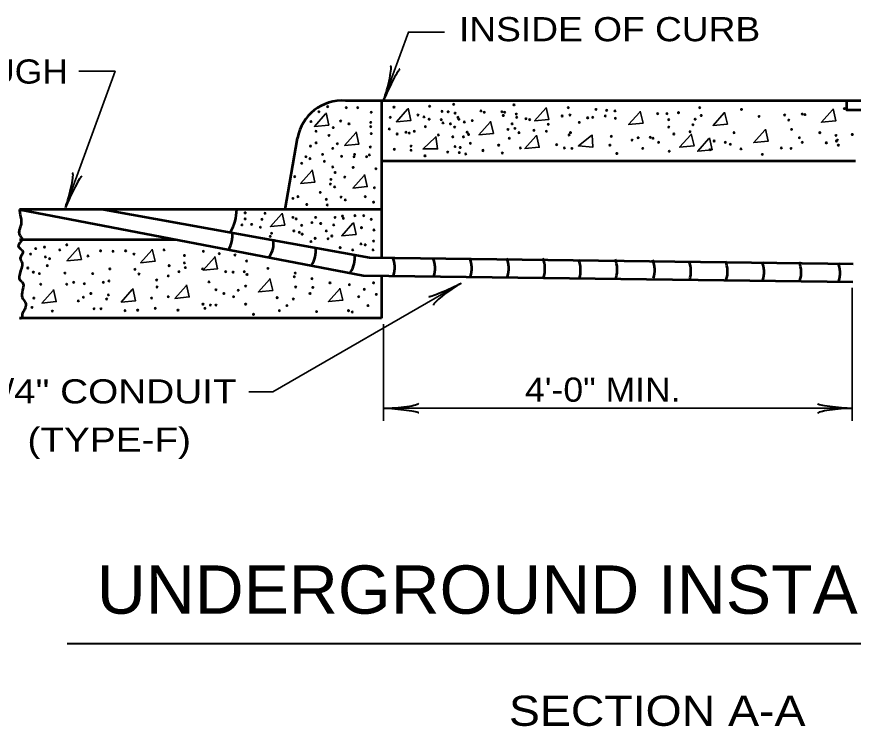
# Model space of a CAD drawing. Extents: x -58 to 622, y -372 to 68.
# Drawn here: x 3.2 to 72.5, y -96.1 to -37.4 of the extents above; entities that cross this region are included whole.
import ezdxf
from ezdxf.enums import TextEntityAlignment as Align

# ---------------------------------------------------------------- set-up
doc = ezdxf.new("R2010")
doc.units = 0
doc.header["$LTSCALE"] = 0.8
doc.layers.add('1', color=7, linetype='Continuous', lineweight=35)

msp = doc.modelspace()

# ---------------------------------------------------------------- linework, layer by layer
at = {"layer": '1', "lineweight": 53}
for p, q in [((95.4567, -44.3181), (30.4567, -44.3181)), ((33.4567, -44.3181), (33.4567, -57.3237)), ((25.4567, -53.3181), (26.4986, -47.4093)), ((72.7067, -49.3181), (33.4567, -49.3181)), ((33.4567, -53.3181), (3.4567, -53.3181)), ((3.4567, -53.3181), (31.9376, -58.7988)), ((10.4567, -53.3181), (32.4567, -57.3053)), ((3.4567, -55.8181), (16.448, -55.8181)), ((32.4567, -57.3053), (72.5202, -57.8181)), ((31.9376, -58.7988), (72.501, -59.318)), ((33.4567, -58.7824), (33.4567, -62.3181)), ((33.4567, -62.3181), (3.4567, -62.3181))]:
    msp.add_line(p, q, dxfattribs=at)
at = {"layer": '1'}
for p, q in [((72.4397, -59.8188), (72.4397, -70.8188)), ((33.6269, -62.8061), (33.6269, -70.8188)), ((33.6609, -69.7865), (72.4412, -69.7865))]:
    msp.add_line(p, q, dxfattribs=at)
at = {"layer": '1', "lineweight": 40}
msp.add_line((7.4085, -89.2559), (100.8059, -89.2559), dxfattribs=at)
at = {"layer": '1'}
for points in [[(33.6255, -44.2669), (35.6776, -38.6287), (38.6776, -38.6287)], [(7.2722, -53.1423), (11.3764, -41.866), (8.3764, -41.866)], [(35.6102, -45.0193), (34.6888, -46.0558), (35.8788, -45.9407), (35.6485, -44.9426)], [(47.0498, -44.9426), (46.1285, -45.9791), (47.3185, -45.8639), (47.0882, -44.8658)], [(70.812, -45.0577), (69.8907, -46.0942), (71.0807, -45.9791), (70.8503, -44.981)], [(28.8155, -45.4032), (27.8942, -46.4397), (29.0842, -46.3246), (28.8538, -45.3265)], [(54.8426, -45.2497), (53.9213, -46.2862), (55.1112, -46.171), (54.8809, -45.1729)], [(61.8292, -45.3264), (60.9079, -46.3629), (62.0979, -46.2477), (61.8676, -45.2497)], [(42.4432, -46.0942), (41.5219, -47.1307), (42.7119, -47.0156), (42.4816, -46.0175)], [(31.3107, -46.9771), (30.3893, -48.0136), (31.5793, -47.8984), (31.349, -46.9003)], [(59.0652, -47.1307), (58.1439, -48.1672), (59.3339, -48.052), (59.1036, -47.0539)], [(65.2073, -46.7468), (64.286, -47.7833), (65.476, -47.6682), (65.2457, -46.6701)], [(37.9037, -47.3589), (36.8955, -48.3112), (38.091, -48.3002), (37.9485, -47.2858)], [(46.2437, -47.2458), (45.3223, -48.2823), (46.5123, -48.1672), (46.282, -47.1691)], [(50.8516, -47.1979), (49.7642, -48.0587), (50.9562, -48.1519), (50.9026, -47.129)], [(60.5674, -47.4546), (59.6461, -48.4911), (60.8361, -48.3759), (60.6058, -47.3778)], [(27.6638, -50.1249), (26.7425, -51.1614), (27.9325, -51.0463), (27.7022, -50.0482)], [(32.0017, -50.5088), (31.0803, -51.5453), (32.2703, -51.4302), (32.04, -50.4321)], [(25.1686, -53.695), (24.2472, -54.7315), (25.4372, -54.6163), (25.2069, -53.6182)], [(31.0803, -54.4628), (30.159, -55.4993), (31.349, -55.3842), (31.1187, -54.3861)], [(8.3163, -56.5358), (7.3949, -57.5722), (8.5849, -57.4571), (8.3546, -56.459)], [(14.4199, -56.6893), (13.4986, -57.7258), (14.6886, -57.6107), (14.4582, -56.6126)], [(19.6023, -57.3035), (18.681, -58.34), (19.871, -58.2248), (19.6407, -57.2267)], [(17.2607, -59.6452), (16.3393, -60.6817), (17.5293, -60.5665), (17.299, -59.5684)], [(40.0432, -59.4234), (24.4548, -68.4234), (22.4548, -68.4234)], [(24.1705, -59.1077), (23.2492, -60.1442), (24.4392, -60.0291), (24.2088, -59.031)], [(6.2432, -60.0291), (5.3219, -61.0656), (6.5119, -60.9504), (6.2816, -59.9523)], [(12.8077, -59.9523), (11.8863, -60.9888), (13.0763, -60.8737), (12.846, -59.8756)], [(29.9671, -59.9139), (29.0457, -60.9504), (30.2357, -60.8352), (30.0054, -59.8372)]]:
    msp.add_lwpolyline(points, dxfattribs=at)
at = {"layer": '1', "lineweight": 53}
msp.add_lwpolyline([(71.9567, -44.3181), (71.9567, -45.0681), (86.4567, -45.0681), (86.4567, -44.3181)], dxfattribs=at)
at = {"layer": '1'}
for centre in [(28.9883, -44.8078), (30.5238, -44.8846), (31.4836, -44.8846), (34.4778, -44.8462), (37.4337, -44.7694), (39.4299, -44.6158), (44.4204, -44.6542), (48.9118, -44.8846), (51.2151, -45.0382), (59.814, -44.8846), (63.2689, -45.0382), (71.7911, -44.9613), (28.2589, -45.2301), (32.5968, -45.2685), (34.1707, -45.6908), (36.474, -45.4988), (36.9731, -45.6523), (38.4703, -45.1917), (38.9692, -45.2301), (39.5451, -45.3453), (39.7754, -45.6908), (41.6948, -45.1533), (41.9636, -45.2685), (43.4223, -45.2301), (43.5375, -45.5372), (43.6527, -45.2685), (44.6123, -45.422), (44.6507, -45.6908), (48.4127, -45.5756), (49.0653, -45.4988), (50.5241, -45.7291), (50.9463, -45.6908), (51.9828, -45.5756), (52.098, -45.1149), (52.789, -45.1533), (52.8274, -45.7675), (56.3207, -45.3837), (57.0885, -45.3837), (58.0482, -45.3068), (59.9292, -45.5372), (64.7277, -45.614), (66.839, -45.4988), (68.2977, -45.422), (68.5281, -45.4604), (27.6063, -46.0362), (30.0632, -45.9978), (30.7542, -46.2282), (32.5584, -46.113), (32.5584, -46.4585), (37.0883, -46.4585), (37.3954, -45.8442), (38.3935, -45.8827), (38.547, -46.1514), (39.1612, -46.2282), (39.8522, -45.8442), (40.3128, -46.0746), (40.9655, -45.9594), (44.2668, -46.2282), (45.4185, -45.8059), (45.7256, -45.8827), (47.2611, -46.2666), (49.8331, -46.113), (57.242, -45.8827), (59.2382, -46.3049), (59.4302, -45.8442), (67.1845, -45.9211), (28.0287, -46.8424), (29.449, -46.5353), (32.5968, -47.0343), (34.0939, -46.6505), (34.7465, -47.0727), (35.4759, -46.9192), (35.7447, -46.9959), (36.1669, -46.8424), (38.1632, -47.1495), (39.5067, -46.4969), (40.5432, -46.9192), (40.6583, -47.1111), (43.9213, -46.6888), (44.4972, -46.6121), (44.8427, -46.9576), (46.0711, -46.7656), (47.1076, -46.8424), (48.9886, -47.1495), (49.1037, -46.9576), (57.242, -46.4969), (57.6642, -47.0727), (59.0078, -46.8807), (62.6547, -46.9576), (67.4148, -46.6888), (69.7565, -46.9576), (72.4437, -47.1111), (28.0287, -47.8021), (29.1035, -47.1879), (39.3532, -47.303), (40.2361, -47.303), (40.8119, -47.8405), (44.0365, -47.4182), (52.4819, -47.2647), (54.2093, -47.5718), (54.7084, -47.3798), (55.7065, -47.3414), (55.9368, -47.4182), (56.3975, -47.7637), (61.0041, -47.6485), (61.9253, -47.7637), (68.0675, -47.3798), (68.2977, -47.7637), (70.294, -47.8021), (71.1001, -47.1878), (71.1385, -47.6485), (71.2152, -47.5718), (27.568, -48.0708), (29.4106, -48.2627), (29.7945, -47.8789), (32.52, -48.1476), (34.5162, -48.3395), (35.8982, -48.0708), (35.8982, -48.4163), (39.5451, -48.1092), (39.9674, -48.186), (41.8484, -48.4162), (41.8484, -48.4547), (43.1536, -47.994), (44.9578, -48.2243), (47.9521, -47.9557), (48.6047, -48.2243), (49.2189, -48.2627), (52.3667, -47.994), (55.0922, -48.2627), (57.2804, -48.4931), (60.6586, -48.3779), (62.3477, -47.9172), (63.2306, -48.3011), (66.5703, -48.2243), (67.3765, -48.2627), (71.2921, -47.994), (27.1841, -48.9537), (27.5296, -49.1073), (28.5661, -48.7618), (30.14, -48.9153), (31.1764, -48.9537), (31.2148, -48.7618), (32.2129, -48.9537), (32.4432, -48.8002), (37.0498, -48.877), (38.9309, -48.5698), (39.8906, -48.6082), (40.428, -48.7234), (43.4607, -48.6466), (52.9426, -48.685), (64.9964, -48.7617), (26.8386, -49.4912), (28.7196, -49.3377), (29.4106, -49.7982), (31.0997, -49.8367), (32.9807, -49.9518), (26.2628, -50.6044), (29.6025, -50.2589), (30.4087, -50.6428), (29.2187, -51.2187), (29.2571, -50.8347), (28.3741, -51.9097), (29.5642, -51.449), (32.8655, -51.5257), (26.1092, -52.4087), (26.5315, -52.2551), (28.8732, -52.4854), (30.1016, -52.2935), (30.4471, -52.5238), (32.0977, -52.2551), (32.7888, -52.7157), (27.2608, -52.9078), (28.9499, -52.9461), (22.1552, -53.5987), (22.1552, -54.0977), (23.8059, -53.6371), (26.1092, -53.9826), (26.3779, -54.0977), (27.9902, -53.9826), (29.6025, -53.9826), (30.2167, -53.8674), (30.2935, -54.0593), (31.2532, -53.829), (31.9826, -53.829), (21.8865, -54.5968), (22.6927, -54.5584), (23.4221, -54.7888), (23.5373, -54.1362), (26.8386, -54.6352), (27.6832, -54.4048), (28.4125, -54.4817), (29.4873, -54.5968), (32.5968, -54.1362), (24.3433, -55.2877), (26.186, -55.0958), (26.6467, -55.211), (26.877, -55.3646), (28.8732, -55.0958), (31.7907, -54.8272), (32.8272, -55.0191), (24.2282, -55.5565), (27.6063, -55.9787), (27.9518, -55.7101), (29.0267, -55.7484), (29.3338, -55.5181), (31.7523, -56.1707), (32.7888, -55.9404), (4.8038, -56.5547), (5.5332, -56.4395), (6.8, -56.6698), (7.3758, -56.2475), (10.1782, -56.7466), (11.2147, -56.785), (12.2512, -56.7466), (15.4373, -56.6698), (18.7003, -56.785), (30.0248, -56.4778), (31.0612, -56.6698), (32.0977, -56.2475), (32.7503, -56.6698), (4.3816, -57.0153), (5.61, -57.2457), (5.9555, -57.3992), (9.1417, -57.1688), (12.9422, -57.0153), (17.1264, -57.1305), (20.0055, -56.9769), (21.3107, -57.0921), (4.1513, -58.1669), (5.7636, -57.975), (10.9459, -58.2437), (15.8596, -57.975), (17.1264, -57.7447), (17.2032, -58.1286), (18.6236, -58.2437), (22.2704, -57.5911), (24.0362, -58.2053), (4.6119, -58.5124), (5.1109, -58.6276), (7.2223, -58.5892), (9.5256, -58.6276), (13.0189, -58.2821), (13.3644, -58.666), (15.7828, -58.8196), (16.6657, -58.4741), (20.543, -58.4741), (21.1572, -58.5124), (22.0785, -58.4741), (22.3088, -58.7044), (26.2244, -58.8963), (26.3012, -58.5892), (5.2261, -59.5105), (7.3758, -59.5105), (7.9517, -59.357), (8.8346, -59.4722), (10.4085, -59.357), (10.8692, -59.2418), (14.8232, -59.165), (19.161, -59.3186), (27.6832, -59.0498), (29.1802, -59.3953), (30.7926, -59.5489), (32.7888, -59.3953), (9.372, -60.2782), (14.8615, -59.7408), (19.7368, -59.9712), (20.3894, -60.2782), (21.5794, -60.0096), (22.1937, -59.6641), (26.3396, -59.7408), (27.5296, -60.2782), (27.7599, -59.7792), (32.021, -59.9328), (4.6503, -60.6622), (8.3356, -60.8925), (8.7578, -60.5854), (10.6772, -60.7389), (10.8308, -60.3934), (14.4008, -60.6622), (15.7828, -60.547), (21.1956, -60.547), (24.8041, -60.6238), (26.1477, -60.7389), (31.5603, -60.547), (33.0191, -60.3551), (4.4967, -61.4299), (9.6407, -61.5451), (10.2166, -61.5451), (12.2127, -61.6987), (13.2492, -61.6602), (14.708, -61.5067), (16.589, -61.6602), (18.6619, -61.1612), (18.8155, -61.5067), (19.2762, -61.238), (19.7368, -61.238), (22.1937, -61.1612), (24.996, -61.6987), (25.6102, -61.2764), (30.7158, -61.6987), (32.3281, -61.2764), (6.1858, -61.737), (22.8462, -62.0057), (28.067, -61.7754), (31.0229, -61.8138)]:
    msp.add_circle(centre, 0.0607, dxfattribs=at)
at = {"layer": '1', "lineweight": 53}
for centre, radius, start, end in [((30.1685, -48.0287), 3.7218, 85.55938, 170.41856), ((17.7204, -53.3079), 3.7363, 329.7014, 359.8431), ((18.9283, -55.4966), 2.1707, 327.00343, 7.84739), ((22.3448, -56.0724), 2.1707, 327.00343, 7.84739), ((25.8381, -56.7634), 2.1707, 327.00343, 7.84739), ((29.0627, -57.3393), 2.1707, 327.00343, 7.84739), ((32.382, -58.1124), 2.1707, 342.00343, 22.84739), ((35.7218, -58.1892), 2.1707, 342.00343, 22.84739), ((38.7544, -58.1892), 2.1707, 342.00343, 22.84739), ((41.8254, -58.1892), 2.1707, 342.00343, 22.84739), ((44.8197, -58.2276), 2.1707, 342.00343, 22.84739), ((47.7756, -58.3428), 2.1707, 342.00343, 22.84739), ((50.8083, -58.3044), 2.1707, 342.00343, 22.84739), ((53.9177, -58.3428), 2.1707, 342.00343, 22.84739), ((56.9119, -58.458), 2.1707, 342.00343, 22.84739), ((59.9446, -58.458), 2.1707, 342.00343, 22.84739), ((62.9773, -58.4964), 2.1707, 342.00343, 22.84739), ((66.0484, -58.5347), 2.1707, 342.00343, 22.84739), ((69.2729, -58.5731), 2.1707, 342.00343, 22.84739)]:
    msp.add_arc(centre, radius, start, end, dxfattribs=at)
at = {"layer": '1', "lineweight": 40}
for centre, major_axis, ratio, start_param, end_param in [((33.7391, -43.147), (-0.464, -1.7314), 0.122415, 0.8963533, 3.1415927), ((34.2076, -43.2864), (0.7658, 1.5905), 0.07063, 6.2823074, 8.5597026), ((7.3857, -52.0224), (-0.464, -1.7314), 0.122415, 0.8963533, 3.1415927), ((7.8542, -52.1618), (0.7658, 1.5904), 0.07063, 6.2823074, 8.5597026), ((38.967, -59.8004), (1.609, 0.7261), 0.07063, 3.1407148, 5.41811), ((38.967, -59.8004), (1.609, 0.7261), 0.07063, 3.1407148, 5.41811), ((39.2363, -60.2083), (1.4684, 1.0281), 0.122415, 0.8963533, 3.1415927), ((39.2363, -60.2083), (1.4684, 1.0281), 0.122415, 0.8963533, 3.1415927), ((34.7814, -69.9981), (1.7565, -0.1757), 0.07063, 6.2823074, 8.5597026), ((34.7521, -69.5102), (-1.7857, -0.1562), 0.122415, 0.8963533, 3.1415927), ((71.35, -70.0628), (1.7857, 0.1562), 0.122415, 0.8963533, 3.1415927), ((71.3207, -69.5749), (1.7565, -0.1757), 0.07063, 3.1407148, 5.41811)]:
    msp.add_ellipse(centre, major_axis=major_axis, ratio=ratio, start_param=start_param, end_param=end_param, dxfattribs=at)
at = {"layer": '1', "lineweight": 53}
msp.add_spline([(3.4567, -53.3181), (3.5184, -53.7342), (3.5952, -54.5019), (3.4416, -55.0393), (3.4416, -55.3464), (3.6719, -55.8071), (3.3648, -56.3445), (3.7487, -56.8052), (3.5184, -57.3426), (3.6719, -57.7264), (3.6719, -57.9567), (3.4416, -58.8781), (3.4416, -59.0317), (3.7487, -59.4155), (3.6719, -60.1833), (3.7487, -60.7207), (3.979, -61.1046), (3.8255, -61.7188), (3.6719, -62.1027), (3.6719, -62.333), (3.4567, -62.3181)], degree=3, dxfattribs=at)

# ---------------------------------------------------------------- texts
at = {"layer": '1'}
for s, height, width, p in [('INSIDE OF CURB', 2, 1.15, (39.869, -39.3877)), ('4\'-0" MIN.', 2, 1.1, (45.3354, -69.2403)), ('UNDERGROUND INSTALLATION', 4, 1.05, (9.8662, -86.7986)), ('SECTION A-A', 2.5, 1.15, (44.0028, -96.0832))]:
    msp.add_text(s, height=height, dxfattribs=dict(at, width=width)).set_placement(p)
for s, width, p in [('DRILL THROUGH', 1.1, (-4.5373, -42.8948)), ('3/4" CONDUIT', 1.2, (10.8923, -69.3843)), ('(TYPE-F)', 1.2, (10.8924, -73.3843))]:
    msp.add_text(s, height=2, dxfattribs=dict(at, width=width)).set_placement(p, align=Align.CENTER)

doc.saveas('drawing.dxf')
